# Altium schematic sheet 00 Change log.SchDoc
size 246 x 182 mm
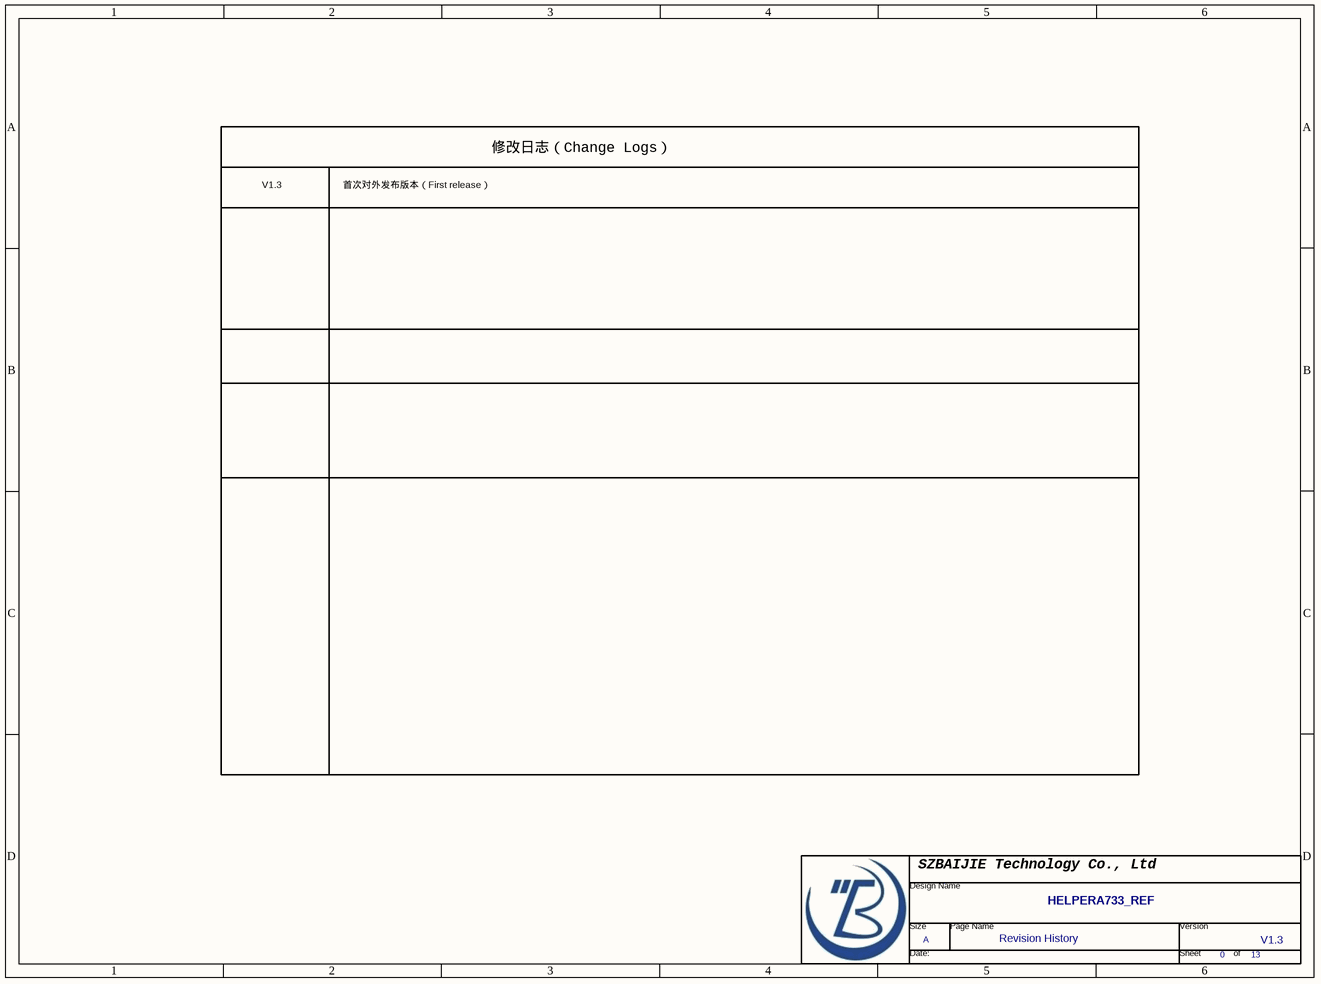
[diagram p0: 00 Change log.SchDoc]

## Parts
*  Page Count: 13  Page Number: 0  Page Size: A  Title: HELPERA733_REF  RevCode: V1.3  Doc: Revision History  (hidden comment: TitleBlock0-BJ)  (graphical)

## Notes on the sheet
- V1.3
- 首次对外发布版本（First release）
- 修改日志（Change Logs）

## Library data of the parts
* = TitleBlock0-BJ: OrgName: szBaijie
